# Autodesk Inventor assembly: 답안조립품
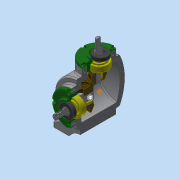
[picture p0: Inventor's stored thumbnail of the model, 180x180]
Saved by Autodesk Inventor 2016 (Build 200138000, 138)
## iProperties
Created: 2021-04
Part Number: 답안조립품
Document SubType Name: Assembly
Designer: User
Author: User
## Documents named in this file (13)
- C:\Users\User\Desktop\710407V1003\답안조립품.iam
- C:\Users\User\Desktop\710407V1003\본체.ipt
- C:\Users\User\Desktop\710407V1003\메인 축.ipt
- 메인 축.ipt
- C:\Users\User\Desktop\710407V1003\서브 축.ipt
- 서브 축.ipt
- C:\Users\User\Desktop\710407V1003\키 5 x 5 x 14.ipt
- C:\Users\User\Desktop\710407V1003\키 4 x 4 x 14.ipt
- C:\Users\User\Desktop\710407V1003\메인 베벨기어.ipt
- C:\Users\User\Desktop\710407V1003\서브 베벨기어.ipt
- C:\Users\User\Desktop\710407V1003\오일실 17 x 32 x 8.ipt
- C:\Users\User\Desktop\710407V1003\커버.ipt
- C:\Users\User\Desktop\710407V1003\베어링 6203.ipt
